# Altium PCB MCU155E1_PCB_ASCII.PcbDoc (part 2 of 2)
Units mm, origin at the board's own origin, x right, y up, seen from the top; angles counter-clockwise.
Board outline 32 x 29 mm, 4 copper layers (Top Layer, Layer 1, Layer 2, Bottom Layer), stack 1.567 mm thick; 102 components, 61 nets, 283 pads, 120 vias.
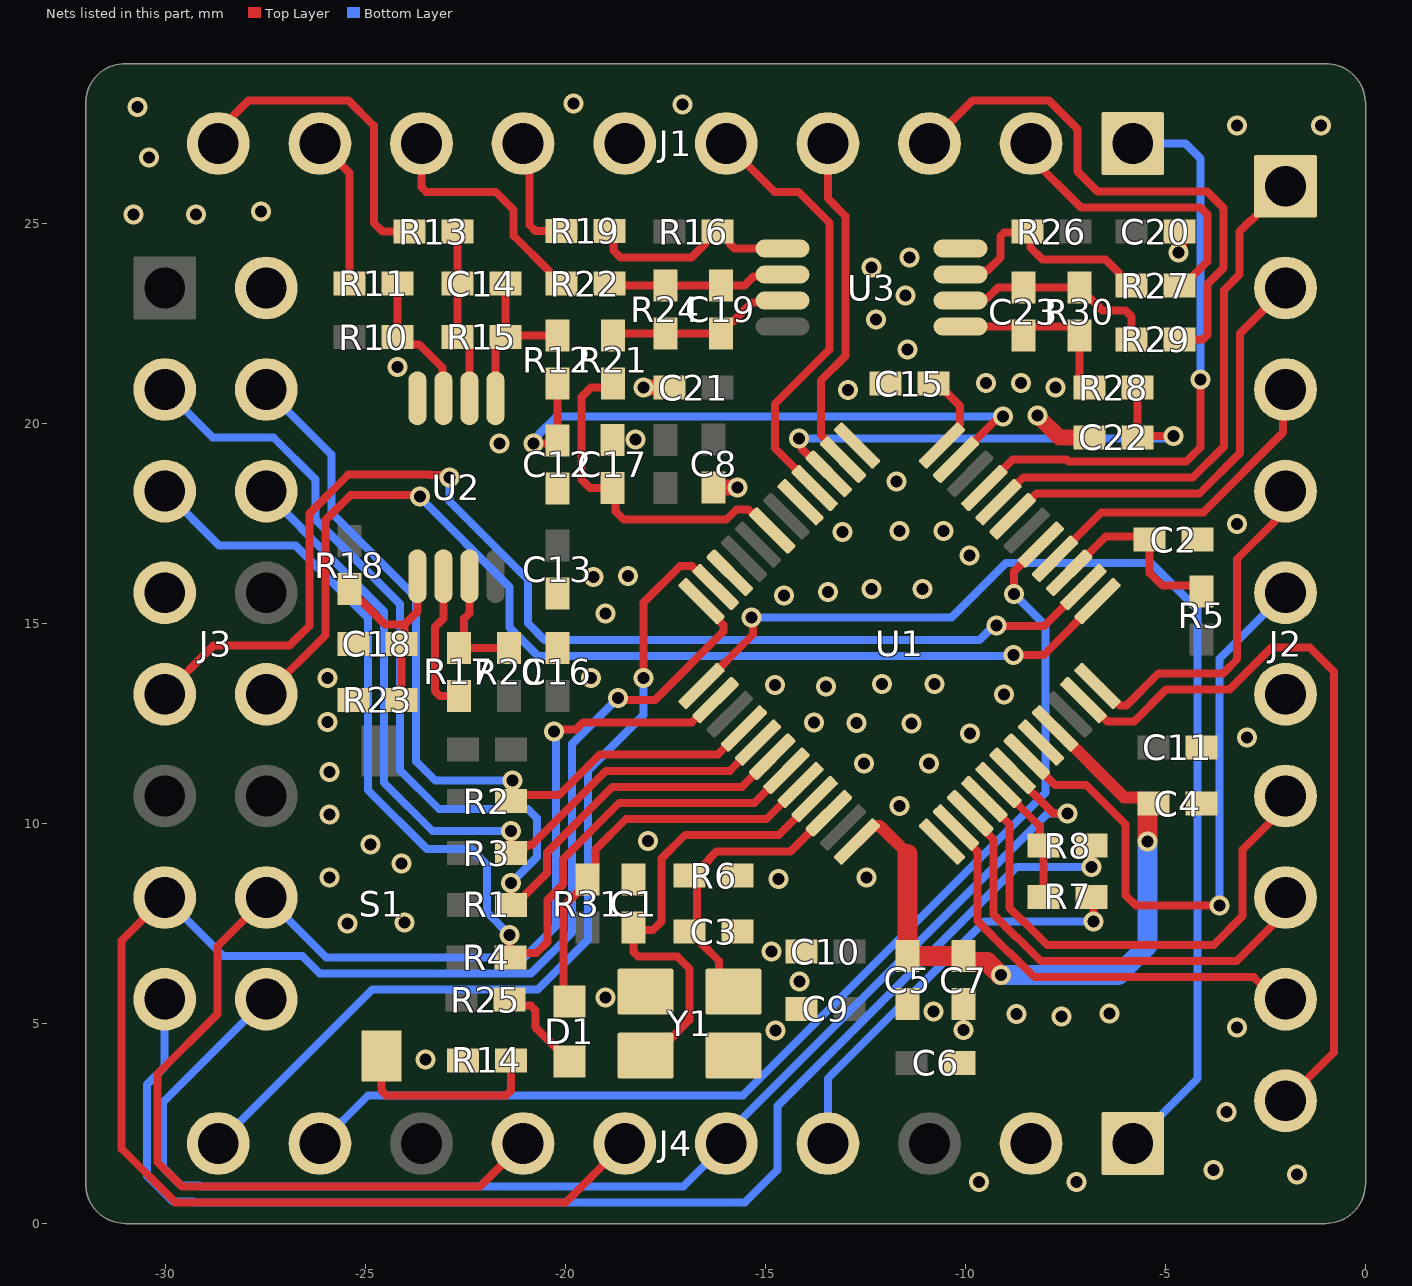
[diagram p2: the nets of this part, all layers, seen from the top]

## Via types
v1: diameter 0.5, hole 0.3, Top Layer to Bottom Layer, tented both sides, 120 vias

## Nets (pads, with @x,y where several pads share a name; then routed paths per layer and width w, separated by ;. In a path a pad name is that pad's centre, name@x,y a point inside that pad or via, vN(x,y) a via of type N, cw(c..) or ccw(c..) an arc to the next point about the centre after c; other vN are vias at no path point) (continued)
GND: C1.1 C2.2 C3.2 C4.1 C5.1 C6.2 C7.1 C8.2 C9.2 C10.2 C11.2 C12.2 C13.2 C15.2 C16.2 C17.2 C18.2 C20.2 C21.2 C22.2 J1.6 J2.6 J3.2 J3.7 J4.2 R6.1 R14.2 R23.1 U1.13 U1.17 U1.22 U1.37 U1.44 U2.4 U3.4 Y1.2 Y1.4 | length 3.6
  Top Layer w0.4: C18.2@-25.501,14.591 -25.401,14.491 C18.2@-25.301,14.491 ; v1(-18.05,20.9) C21.2@-17.4,20.9 ; C8.2@-16.3,18.4 -16.297,18.403 -15.703,18.403 v1(-15.7,18.405) ; v1(-8.2,20.2) -7.656,19.656 C22.2@-6.9,19.656 ; v1(-4.676,24.279) -4.663,24.292 -4.663,24.787 C20.2@-4.65,24.8
  other v1: -9.661,1.041 -7.231,1.041 -1.714,1.225 -3.8,1.343 -3.481,2.794 -23.5,4.1 -14.75,4.83 -10.051,4.833 -3.207,4.9 -7.599,5.179 -8.722,5.237 -6.4,5.256 -10.8,5.3 -19,5.65 -14.15,6.05 -14.85,6.8 -25.45,7.5 -24.024,7.52 -14.67,8.61 -25.9,8.651 -12.479,8.651 -24.1,9 -24.879,9.48 -17.943,9.558 -25.9,10.232 -11.649,10.438 -25.9,11.283 -12.531,11.502 -10.912,11.495 -2.959,12.149 -9.887,12.254 -12.729,12.517 -11.355,12.5 -25.95,12.544 -13.788,12.531 -9.038,13.226 -13.488,13.43 -14.768,13.465 -12.088,13.493 -10.77,13.493 -19.361,13.64 -25.95,13.644 -19,15.256 -14.533,15.705 -13.434,15.79 -12.35,15.86 -11.076,15.86 -19.294,16.163 -18.437,16.187 -9.9,16.703 -13.08,17.293 -11.649,17.312 -10.551,17.312 -3.207,17.491 -11.722,18.551 -21.65,19.5 -18.25,19.6 -12.932,20.843 -7.75,20.9 -9.493,21.01 -8.613,21.01 -24.206,21.408 -11.45,21.85 -12.233,22.606 -11.499,23.202 -12.35,23.9 -11.4,24.15 -30.8,25.224 -29.24,25.224 -27.608,25.3 -30.417,26.646 -3.207,27.454 -1.108,27.454 -30.698,27.909 -17.077,27.975 -19.801,27.998
IPM_FAULT: J4.1 U1.25 | length 28.5
  Top Layer w0.2: U1.25@-16.6,13.439 -15.308,14.731 -15.308,15.108 v1(-15.35,15.15)
  Bottom Layer w0.2: v1(-15.35,15.15) -10.35,15.15 -8.985,16.515 -5.365,16.515 -4.2,15.35 -4.2,3.62 J4.1@-5.82,2
IU_AD: C12.1 R12.2 U1.11 | length 15.7
  Top Layer w0.2: v1(-20.8,19.5) -20.277,19.5 C12.1@-20.2,19.577 R12.2@-20.2,21 ; U1.11@-10.236,19.096 -9.218,20.114 -9.12,20.114 v1(-9.063,20.171)
  Bottom Layer w0.2: v1(-20.8,19.5) -20.8,19.581 -20.663,19.718 -20.663,19.741 -20.232,20.171 v1(-9.063,20.171)
IU_N: J1.10 R13.1 | length 8.2
  Top Layer w0.2: J1.10@-28.68,27 -28.68,27.32 -27.925,28.075 -25.423,28.075 -24.793,27.445 -24.793,25.014 -24.579,24.8 R13.1@-23.9,24.8
IU_P: J1.9 R11.1 | length 3.8
  Top Layer w0.2: J1.9@-26.14,27 -25.4,26.26 R11.1@-25.4,23.5
IV_AD: C17.1 R21.2 U1.19 | length 8.7
  Top Layer w0.2: R21.2@-18.811,21 -18.911,20.9 -19.361,20.9 -19.6,20.661 -19.6,18.599 -19.39,18.388 C17.1@-18.82,18.388 -18.747,18.316 -18.747,17.806 -18.537,17.596 -15.979,17.596 -15.719,17.855 -15.43,17.855 U1.19@-14.903,17.328
IV_N: J1.8 R22.1 | length 6
  Top Layer w0.2: J1.8@-23.6,27 -23.6,25.911 -23.483,25.794 -21.746,25.794 -21.295,25.342 -21.295,24.693 -20.401,23.8 -20.401,23.7 -20.201,23.5 R22.1@-20.101,23.5
IV_P: J1.7 R19.1 | length 3
  Top Layer w0.2: J1.7@-21.06,27 -20.895,26.835 -20.895,24.958 -20.751,24.814 R19.1@-20.101,24.814
IW_AD: C22.1 R28.2 U1.15 | length 12.8
  Top Layer w0.2: v1(-14.16,19.621) -14.103,19.564 -14.103,19.38 -13.466,18.743 U1.15@-13.418,18.743 ; R28.2@-5.7,20.9 C22.1@-5.7,19.656 -5.671,19.685 v1(-4.8,19.685)
  Bottom Layer w0.2: v1(-14.16,19.621) -4.945,19.621 -4.881,19.685 v1(-4.8,19.685)
IW_N: J1.3 R29.1 | length 13.6
  Top Layer w0.2: J1.3@-10.9,27 -9.825,28.075 -7.915,28.075 -7.2,27.36 -7.2,26.3 -6.7,25.8 -3.96,25.8 -3.55,25.39 -3.55,23.891 -3.95,23.491 -3.95,22.219 -4.067,22.101 R29.1@-4.65,22.101
IW_P: J1.2 R27.1 | length 7.5
  Top Layer w0.2: J1.2@-8.36,27 -8.36,26.646 -7.114,25.4 -6.374,25.4 -5.326,25.4 -4.126,25.4 -3.95,25.224 -3.95,24.056 -4.35,23.656 -4.35,23.651 -4.55,23.451 R27.1@-4.65,23.451
LED1C: D1.2 R31.1 U1.32 | length 10.3
  Top Layer w0.2: D1.2@-19.9,5.55 -20.05,5.7 -20.05,7.924 -19.674,8.3 -19.65,8.3 -19.65,8.648 -19.4,8.898 R31.1@-19.38,8.898 ; R31.1@-19.45,8.6 -19.25,8.8 -19.25,9.35 -18.482,10.118 -14.971,10.118 U1.32@-14.125,10.964
MISC_IO: J4.9 U1.5 | length 28.6
  Top Layer w0.2: v1(-8.787,15.737) -8.787,16.303 U1.5@-8.114,16.975
  Bottom Layer w0.2: J4.9@-26.14,2 -24.933,3.207 -15.562,3.207 -8,10.769 -8,14.951 v1(-8.787,15.737)
MOTOR_TEMP_AD: J2.3 U1.4 | length 8.1
  Top Layer w0.2: U1.4@-7.761,16.621 -6.6,17.782 -4.054,17.782 -2.061,19.775 -2.061,20.789 J2.3@-2,20.85
NetC1_2: C1.2 U1.33 Y1.3 | length 11.7
  Top Layer w0.2: C1.2@-18.3,7.398 -18.3,6.792 -18.183,6.675 -17.206,6.675 -16.9,6.369 -16.9,5.094 -17.403,4.591 -17.403,4.535 -17.878,4.06 Y1.3@-18.003,4.06 ; C1.2@-18.216,7.334 -17.817,7.334 -17.6,7.551 -17.6,9.123 -17.005,9.718 -14.664,9.718 U1.33@-13.771,10.611
NetC3_1: C3.1 R6.2 U1.34 Y1.1 | length 7.4
  Top Layer w0.2: C3.1@-16.9,7.3 -16.8,7.3 -16.6,7.1 -16.6,7 -16.158,6.558 -16.158,6.158 Y1.1@-15.8,5.8 ; C3.1@-16.71,7.3 -16.71,8.55 -16.68,8.58 -16.68,8.819 -16.4,9.098 -16.4,9.123 -16.224,9.298 -14.377,9.298 U1.34@-13.418,10.257
NetC4_2: C4.2 C5.2 C7.2 U1.36 U1.45 | length 17.5
  Top Layer w0.3: U1.36@-12.711,9.55 -12.322,9.939 -12.145,9.939 -11.448,9.243 ; U1.45@-7.761,12.379 -6.032,10.65 -5.45,10.65 C4.2@-5.437,10.637
  Top Layer w0.5: -11.448,9.243 C5.2@-11.448,6.683 C7.2@-10.051,6.683 -10.051,6.583 -10.001,6.533 -9.451,6.533 -9.133,6.215 v1(-9.114,6.215) ; v1(-5.45,9.55) -5.45,10.157 -5.45,10.45 -5.4,10.5 C4.2@-5.3,10.5
  Bottom Layer w0.5: v1(-9.114,6.215) -6.179,6.215 -5.45,6.945 v1(-5.45,9.55)
NetC14_1: C14.1 R13.2 R15.1 U2.2 | length 4.3
  Top Layer w0.2: R13.2@-22.7,24.8 C14.1@-22.7,23.5 R15.1@-22.7,22.158 -22.602,22.158 -22.402,21.958 U2.2@-22.402,20.631
NetC14_2: C14.2 R12.1 R15.2 U2.1 | length 4.3
  Top Layer w0.2: U2.1@-21.752,20.631 -21.752,21.958 -21.552,22.158 R15.2@-21.5,22.158 ; C14.2@-21.5,23.5 R15.2@-21.5,22.158 ; R12.1@-20.2,22.2 -21.458,22.2 R15.2@-21.5,22.158
NetC15_1: C15.1 U1.12 | length 2.1
  Top Layer w0.2: C15.1@-10.8,21 -10.7,21 -10.138,20.438 -10.138,19.972 -10.589,19.52 U1.12@-10.589,19.45
NetC18_1: C18.1 R18.1 R23.2 U2.5 | length 5.1
  Top Layer w0.2: R18.1@-25.399,15.863 -25.399,15.763 -25.199,15.563 -25.099,15.563 -24.511,14.974 -24.026,14.974 ; C18.1@-24.101,14.491 -24.026,14.566 -24.026,14.974 ; R23.2@-24.1,13.094 C18.1@-24.101,14.491 ; U2.5@-23.702,16.181 -23.702,15.298 -24.026,14.974
NetC19_1: C19.1 R22.2 R24.1 U3.6 | length 4.4
  Top Layer w0.2: R22.2@-18.801,23.5 -18.753,23.452 R24.1@-17.498,23.451 -15.528,23.452 -15.303,23.677 -14.623,23.677 U3.6@-14.575,23.725
NetC19_2: C19.2 R21.1 R24.2 U3.7 | length 4.7
  Top Layer w0.2: R21.1@-18.811,22.2 -18.759,22.252 R24.2@-17.498,22.251 C19.2@-16.113,22.252 -16.113,22.352 -15.913,22.552 -15.813,22.552 -15.337,23.027 -14.623,23.027 U3.7@-14.575,23.075
NetC23_1: C23.1 R29.2 R30.1 U3.2 | length 5.3
  Top Layer w0.2: U3.2@-10.125,23.075 -10.087,23.113 -9.495,23.113 -9.441,23.168 -9.419,23.168 -9.187,23.4 C23.1@-8.548,23.4 R30.1@-7.146,23.4 -7.146,23.3 -6.971,23.125 -6.871,23.125 -6.572,22.826 -5.996,22.826 -5.85,22.679 R29.2@-5.85,22.101
NetC23_2: C23.2 R28.1 R30.2 U3.1 | length 4.5
  Top Layer w0.2: U3.1@-10.125,22.425 -7.346,22.425 -7.146,22.225 R30.2@-7.146,22.2 -7.146,21.1 -6.946,20.9 R28.1@-6.9,20.9
NetD1_1: D1.1 R25.2 | length 2.4
  Top Layer w0.2: R25.2@-21.4,5.6 -21.246,5.446 -20.867,5.446 -20.75,5.329 -20.75,4.9 D1.1@-19.9,4.05
NetR10_1: R10.1 R11.2 U2.3 | length 3.6
  Top Layer w0.2: R11.2@-24.2,23.5 R10.1@-24.2,22.158 -24.018,21.976 -23.658,21.976 -23.079,21.397 -23.079,20.658 U2.3@-23.052,20.631
NetR14_1: R14.1 S1.2 | length 5
  Top Layer w0.2: S1.2@-24.6,4.19 -24.6,3.324 -24.483,3.207 -21.482,3.207 -21.365,3.324 R14.1@-21.365,4.082
NetR16_1: R16.1 R19.2 U3.5 | length 5.4
  Top Layer w0.2: R19.2@-18.901,24.814 -18.806,24.719 -18.806,24.332 -18.626,24.152 -16.848,24.152 -16.5,24.5 -16.5,24.6 -16.3,24.8 R16.1@-16.2,24.8 -16.1,24.8 -15.9,24.6 -15.9,24.5 -15.775,24.375 U3.5@-14.575,24.375
NetR17_1: R17.1 R20.1 U2.7 | length 3.2
  Top Layer w0.2: U2.7@-22.402,16.181 -22.402,15.256 -22.533,15.125 -22.533,14.624 -22.664,14.493 R17.1@-22.664,14.393 R20.1@-21.407,14.393
NetR17_2: R17.2 U2.6 | length 3.6
  Top Layer w0.2: U2.6@-23.052,16.181 -23.052,15.129 -23.264,14.917 -23.264,13.31 -23.147,13.193 R17.2@-22.664,13.193
NetR26_1: R26.1 R27.2 U3.3 | length 5.8
  Top Layer w0.2: U3.3@-10.125,23.725 -9.621,23.725 -9.521,23.825 -9.447,23.825 -9.125,24.147 -9.125,24.683 -9.033,24.775 -8.475,24.775 R26.1@-8.45,24.8 -8.371,24.721 -8.371,24.396 -8.075,24.1 -6.499,24.1 -6.15,23.751 -6.15,23.651 -5.95,23.451 R27.2@-5.85,23.451
PC_RX: J3.9 U1.2 | length 30.1
  Top Layer w0.2: J3.9@-30.02,13.23 -28.801,14.449 -26.897,14.449 -26.405,14.941 -26.405,17.713 -26.399,17.718 -26.399,17.753 -25.432,18.72 -23.404,18.72 -23.393,18.71 -22.957,18.71 v1(-22.9,18.652) ; v1(-9.23,14.951) -9.217,14.938 -8.03,14.938 U1.2@-7.054,15.914
  Bottom Layer w0.2: v1(-22.9,18.652) -22.9,18.055 -20.932,16.086 -20.932,14.997 -20.525,14.59 -9.647,14.59 -9.287,14.951 v1(-9.23,14.951)
PC_TX: J3.10 U1.1 | length 27.4
  Top Layer w0.2: J3.10@-27.48,13.23 -26.001,14.709 -26.001,15.982 -25.999,15.984 -25.999,17.587 -25.379,18.207 -23.669,18.207 v1(-23.632,18.17) ; v1(-8.805,14.22) -8.041,14.22 U1.1@-6.7,15.561
  Bottom Layer w0.2: v1(-23.632,18.17) -23.632,18.149 -21.4,15.917 -21.4,14.9 -20.69,14.19 -8.834,14.19 v1(-8.805,14.22)
PWM_UH: J2.7 U1.40 | length 12.9
  Top Layer w0.2: U1.40@-9.529,10.611 -8.9,9.982 -8.9,7.891 -8.574,7.565 -8.555,7.565 -7.947,6.958 -3.803,6.958 -3.075,7.686 -3.075,9.346 -2,10.421 J2.7@-2,10.69
PWM_UL: J2.8 U1.39 | length 11.4
  Top Layer w0.2: U1.39@-9.882,10.257 -9.882,10.187 -9.3,9.604 -9.3,7.726 -8.74,7.165 -8.72,7.165 -8.113,6.558 -3.227,6.558 -2,7.785 J2.8@-2,8.15
PWM_VH: J2.9 U1.38 | length 11.1
  Top Layer w0.2: U1.38@-10.236,9.904 -10.236,9.833 -9.7,9.297 -9.7,7.56 -8.906,6.765 -8.886,6.765 -8.278,6.158 -2.792,6.158 -2.244,5.61 J2.9@-2,5.61
PWM_VL: J2.10 U1.47 | length 18.7
  Top Layer w0.2: U1.47@-7.054,13.086 -6.983,13.086 -6.45,12.553 -5.782,12.553 -4.985,13.35 -3.4,13.35 -2.35,14.4 -1.394,14.4 -0.794,13.8 -0.794,4.276 J2.10@-2,3.07
PWM_WH: J2.4 U1.48 | length 8.9
  Top Layer w0.2: U1.48@-6.7,13.439 -6.63,13.439 -6.143,12.953 -5.977,12.953 -5.18,13.75 -3.566,13.75 -3.207,14.109 -3.207,16.619 -2.258,17.567 -2.258,18.052 J2.4@-2,18.31
PWM_WL: J2.5 U1.43 | length 15.9
  Top Layer w0.2: U1.43@-8.468,11.672 -7.761,10.964 -6.983,10.964 -6,9.981 -6,8.209 -5.741,7.95 v1(-3.65,7.95)
  Bottom Layer w0.2: v1(-3.65,7.95) -3.65,14.12 J2.5@-2,15.77
RELAY: J4.10 U1.23 | length 22.8
  Top Layer w0.2: v1(-18.05,13.64) -18.05,15.525 -17.133,16.441 -16.844,16.441 -16.317,15.914 U1.23@-16.246,15.914
  Bottom Layer w0.2: J4.10@-28.68,2 -24.83,5.85 -20.694,5.85 -19.44,7.105 -19.44,11.327 -18.05,12.717 v1(-18.05,13.64)
SPI_CLK: J3.13 J4.6 U1.24 | length 42.6
  Top Layer w0.2: J3.13@-30.02,8.15 -31.095,7.075 -31.095,1.867 -29.753,0.525 -19.995,0.525 J4.6@-18.52,2 ; v1(-18.689,13.137) -18.643,13.09 -17.762,13.09 -16.055,14.797 -16.055,14.963 -16.6,15.507 U1.24@-16.6,15.561
  Bottom Layer w0.2: J3.13@-30.02,8.15 -28.555,6.685 -26.581,6.685 -26.146,6.25 -20.86,6.25 -19.84,7.27 -19.84,11.986 v1(-18.689,13.137)
SPI_PICO: J3.14 J4.7 U1.26 | length 35
  Top Layer w0.2: J3.14@-27.48,8.15 -28.7,6.93 -28.7,5.237 -30.204,3.732 -30.204,1.542 -29.587,0.925 -22.135,0.925 J4.7@-21.06,2 ; v1(-20.289,12.303) -20.24,12.353 -19.739,12.353 -19.561,12.531 -16.844,12.531 -16.289,13.086 U1.26@-16.246,13.086
  Bottom Layer w0.2: J3.14@-27.48,8.15 -25.98,6.65 -21.026,6.65 -20.24,7.436 -20.24,12.254 v1(-20.289,12.303)
SPI_POCI: R7.2 R8.2 U1.41 | length 3.3
  Top Layer w0.2: U1.41@-9.175,10.964 -8.144,9.933 -8.144,9.544 R8.2@-8.05,9.45 R7.2@-8.05,8.165
SPI_POCI(AI): J4.4 R7.1 | length 10.6
  Top Layer w0.2: R7.1@-6.85,8.165 -6.8,8.115 v1(-6.8,7.55) v1@-6.748,7.55
  Bottom Layer w0.2: J4.4@-13.44,2 -13.44,3.632 -9.522,7.55 v1(-6.8,7.55)
SPI_POCI(DAC): J3.15 R8.1 | length 33.4
  Top Layer w0.2: v1(-6.85,8.915) R8.1@-6.85,9.45
  Bottom Layer w0.2: J3.15@-30.02,5.61 -30.02,3.917 -30.46,3.477 -30.46,1.194 -29.816,0.55 -29.316,0.55 -29.291,0.525 -15.518,0.525 -14.7,1.343 -14.7,2.937 -8.722,8.915 v1(-6.85,8.915)
SPI_PTE: J3.16 J4.5 U1.42 | length 33.9
  Top Layer w0.2: U1.42@-8.822,11.318 -8.822,11.272 -7.8,10.25 v1(-7.45,10.25)
  Bottom Layer w0.2: J3.16@-27.48,5.61 -30.06,3.03 -30.06,1.398 -29.612,0.95 -29.15,0.95 -29.125,0.925 -17.055,0.925 J4.5@-15.98,2 -15.98,2.223 -7.953,10.25 v1(-7.45,10.25)
TCK: J3.4 R2.1 U1.28 | length 20.5
  Top Layer w0.2: R2.1@-21.365,10.557 R2.1@-21.33,10.592 ; v1(-21.33,11.078) R2.1@-21.33,10.592 ; U1.28@-15.539,12.379 -16.187,11.731 -19.14,11.731 -20.157,10.714 -21.208,10.714 R2.1@-21.33,10.592
  Bottom Layer w0.2: J3.4@-27.48,20.85 -25.85,19.22 -25.85,17.768 -23.734,15.652 -23.734,11.556 -23.256,11.078 v1(-21.33,11.078)
TDI: J3.5 R4.1 U1.31 | length 26.8
  Top Layer w0.2: v1(-21.4,7.217) -21.4,6.666 R4.1@-21.381,6.647 -21.269,6.759 -20.731,6.759 -20.45,7.039 -20.45,8.09 -20.065,8.475 -20.065,9.109 -18.656,10.518 -15.278,10.518 U1.31@-14.478,11.318
  Bottom Layer w0.2: J3.5@-30.02,18.31 -28.662,16.952 -26.749,16.952 -24.934,15.138 -24.934,10.834 -23.461,9.361 -22.364,9.361 -21.965,8.962 -21.965,7.782 v1(-21.4,7.217)
TDO: J3.6 R3.1 U1.29 | length 19.9
  Top Layer w0.2: v1(-21.365,9.807) R3.1@-21.365,9.262 -21.132,9.262 -20.932,9.462 -20.843,9.462 -18.988,11.318 -15.893,11.318 U1.29@-15.286,11.925
  Bottom Layer w0.2: J3.6@-27.48,18.31 -27.48,18.266 -26.6,17.386 -26.6,17.369 -24.534,15.303 -24.534,11.022 -23.319,9.807 v1(-21.365,9.807)
TIPM_AD: J2.2 U1.7 | length 10.9
  Top Layer w0.2: U1.7@-8.822,17.682 -8.798,17.682 -8.224,18.256 -4.145,18.256 -3.141,19.26 -3.141,22.249 J2.2@-2,23.39
TMS: J3.3 R1.1 U1.30 | length 27.6
  Top Layer w0.2: v1(-21.365,8.512) R1.1@-21.365,7.967 -21.265,7.967 -20.465,8.767 -20.465,9.275 -18.822,10.918 -15.586,10.918 U1.30@-14.832,11.672
  Bottom Layer w0.2: J3.3@-30.02,20.85 -28.827,19.657 -27.306,19.657 -26.25,18.6 -26.25,17.602 -24.134,15.486 -24.134,11.334 -23.157,10.357 -20.939,10.357 -20.715,10.133 -20.715,9.162 v1(-21.365,8.512)
VDC_AD: J2.1 U1.8 | length 13.4
  Top Layer w0.2: U1.8@-9.175,18.036 -8.555,18.656 -4.311,18.656 -3.541,19.426 -3.541,23.334 -3.15,23.725 -3.15,24.8 -2.89,25.06 -2.87,25.06 J2.1@-2,25.93
VU_AD: J1.4 U1.14 | length 8.6
  Top Layer w0.2: J1.4@-13.44,27 -13.44,25.624 -13,25.184 -13,21.691 -13.61,21.081 -13.61,19.713 -13.064,19.167 U1.14@-13.064,19.096
VV_AD: J1.1 U1.9 | length 14.9
  Top Layer w0.2: U1.9@-9.529,18.389 -8.822,19.096 -7.464,19.096 -7.424,19.056 -4.477,19.056 -4.126,19.407 v1(-4.126,21.1)
  Bottom Layer w0.2: J1.1@-5.82,27 -4.5,27 -4.126,26.626 v1(-4.126,21.1)
VW_AD: J1.5 U1.16 | length 11
  Top Layer w0.2: J1.5@-15.98,27 -14.774,25.794 -14.175,25.794 -13.4,25.019 -13.4,21.857 -14.763,20.494 -14.763,19.381 U1.16@-13.771,18.389
XRSn: C2.1 R5.1 U1.3 | length 4.7
  Top Layer w0.2: U1.3@-7.407,16.268 -6.504,17.171 -5.471,17.171 C2.1@-5.4,17.1 -5.4,16.269 -5.081,15.95 -4.25,15.95 R5.1@-4.1,15.8
pads on no net: J3.8 J3.11 J3.12 J4.8 LBL1.0 M46.1 M46.2 M47.1 M49.1 M49.2 M49_1.2 M49_2.2 M50.1 M50.2 M51.1 M51.2 M52.1 M52.2 M53.1 M54.1 M55.1 M56.2 M56_1.2 M56_2.2 M57.2 M57_1.2 M57_2.2 M57_2_1.2 M57_2_2.2 M58.2 M58_1.2 M58_2.2 M58_2_1.2 M59.2 M59_1.2 M60.2 M60_1.2 M61.2 U1.6 U1.10 U1.20 U1.21

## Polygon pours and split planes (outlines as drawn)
GND on Top Layer "T-G" (solid, remove dead copper, pour order 0): -30.6,28.6 ccw(c-30.6,27.6) -31.6,27.6 -31.6,1.4 ccw(c-30.6,1.4) -30.6,0.4 -1.4,0.4 ccw(c-1.4,1.4) -0.4,1.4 -0.4,27.6 ccw(c-1.4,27.6) -1.4,28.6
GND on Layer 1 "G1-G" (solid, remove dead copper, pour order 1): -30.6,28.6 ccw(c-30.6,27.6) -31.6,27.6 -31.6,1.4 ccw(c-30.6,1.4) -30.6,0.4 -1.4,0.4 ccw(c-1.4,1.4) -0.4,1.4 -0.4,27.6 ccw(c-1.4,27.6) -1.4,28.6
GND on Layer 2 "G2-G" (solid, remove dead copper, pour order 2): -30.6,28.6 ccw(c-30.6,27.6) -31.6,27.6 -31.6,1.4 ccw(c-30.6,1.4) -30.6,0.4 -1.4,0.4 ccw(c-1.4,1.4) -0.4,1.4 -0.4,27.6 ccw(c-1.4,27.6) -1.4,28.6
GND on Bottom Layer "B-G" (solid, remove dead copper, pour order 3): -30.6,28.6 ccw(c-30.6,27.6) -31.6,27.6 -31.6,1.4 ccw(c-30.6,1.4) -30.6,0.4 -1.4,0.4 ccw(c-1.4,1.4) -0.4,1.4 -0.4,27.6 ccw(c-1.4,27.6) -1.4,28.6

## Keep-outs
Keep-Out Layer:
  text ".Layer_Name" at -107.864,-32.255 h1.52

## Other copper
Top Layer:
  text ".Layer_Name" at -107.864,-32.255 h1.52
Bottom Layer:
  text ".Layer_Name" at -107.864,-32.255 h1.52

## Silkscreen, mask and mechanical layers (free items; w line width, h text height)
Top Overlay:
  lines w0.1: -9.14,4.717 -3.19,4.717 ; -9.14,5.376 -3.19,5.376 ; -6.445,3.991 -6.445,6.741 ; -9.19,3.97 -3.19,3.97 -3.19,6.77 -9.19,6.77 -9.19,3.97
  text "1" at -26.773,10.521 h0.4
  text "S1 /  / 1-OFF / 0-ON" at -9.355,4.106 h0.4
  text "Boot Mode / Flash / SCI/Wait" at -6.321,4.106 h0.4
  text "0" at -26.773,3.907 h0.4
  text "拼板" at 263.809,-23.566 h5
  text ".Layer_Name" at -107.864,-32.255 h1.52
Bottom Overlay:
  text "'.PRJ_Number'.PCB_Rev" at -15.867,10.118 h1.52 r270
  text "'.PRJ_Title'" at -14.15,4.757 h1.52 r270
  text ".Layer_Name" at -107.864,-32.255 h1.52
Top Paste:
  text ".Layer_Name" at -107.864,-32.255 h1.52
Bottom Paste:
  text ".Layer_Name" at -107.864,-32.255 h1.52
Top Solder:
  text ".Layer_Name" at -107.864,-32.255 h1.52
  text ".Layer_Name" at -107.864,-32.255 h1.52
Bottom Solder:
  text ".Layer_Name" at -107.864,-32.255 h1.52
Drill Guide:
  text ".Layer_Name" at -107.864,-32.255 h1.52
M1 Board Outline:
  drawing of 210 lines, arcs and shapes, not listed
  text ".Layer_Name" at -107.864,-32.255 h1.52
M2 Board Dimensions:
  rectangle: -122.52,-17.435 -119.345,-14.26
  rectangle: -119.345,-20.61 -109.82,-17.435
  lines w0.178: -122.52,-17.435 -97.12,-17.435 ; -119.345,-20.61 -119.345,-14.26 ; -116.17,-20.61 -116.17,-14.26 ; -109.82,-20.61 -109.82,-14.26 ; -103.47,-20.61 -103.47,-14.26 ; -122.52,-20.61 -97.12,-20.61 -97.12,-14.26 -122.52,-14.26 -122.52,-20.61
  text ".Layer_Name" at -107.864,-32.255 h1.52
M3 3D STEP Top:
  text ".Layer_Name" at -107.864,-32.255 h1.52
M4 3D STEP Bottom:
  text ".Layer_Name" at -107.864,-32.255 h1.52
M5 Assembly Top:
  lines w0.254: -129.937,-34.076 37.703,-34.076 ; -129.937,-28.911 37.754,-28.911 ; -129.937,-23.746 -129.937,-39.24 -28.21,-39.24 37.754,-39.24 37.754,-23.746 -129.924,-23.746 -129.924,-39.24 -89.906,-39.24 ; -67.326,-39.24 -67.326,-23.746 ; -35.144,-28.911 -35.144,-23.746 ; -13.808,-28.911 -13.808,-23.746 ; 1.991,-39.406 1.991,-34.254
  text "COMPONENTS MARKED 'DNP' SHOULD NOT BE POPULATED." at -93.221,-18.539 h0.8
  text "ASSEMBLY VARIANT:" at -93.234,-21.473 h0.8
  text ".VariantName" at -66.919,-21.473 h0.8
  text "PCB VIEWED FROM TOP SIDE" at -128.324,-27.103 h1.52
  text "BOARD #:" at -65.421,-27.103 h1.52
  text ".PRJ_Number" at -51.565,-27.103 h1.52
  text "REV:" at -30.115,-27.103 h1.52
  text ".PCB_Rev" at -22.711,-27.103 h1.52
  text "SVN REV:" at -8.83,-27.103 h1.52
  text ".VersionControl_RevNumber" at 4.023,-27.103 h1.52
  text "TID #:" at -65.421,-32.268 h1.52
  text ".TID" at -51.565,-32.268 h1.52
  text "PLOT NAME =" at -128.324,-37.484 h1.52
  text ".plot_File_Name" at -107.864,-37.484 h1.52
  text "GENERATED    :" at -65.37,-37.484 h1.52
  text ".Print_Date" at -43.285,-37.484 h1.52
  text ".Print_Time" at -24.768,-37.484 h1.52
  text "TEXAS INSTRUMENTS" at 7.35,-37.484 h1.52
M6 Assembly Bottom:
  lines w0.254: -129.95,-28.924 37.741,-28.924 ; -129.899,-34.088 37.741,-34.088 ; -94.186,-39.418 -94.186,-34.266 ; -78.388,-28.924 -78.388,-23.759 ; -57.052,-28.924 -57.052,-23.759 ; -24.87,-39.253 -24.87,-23.759 ; -2.289,-39.253 37.729,-39.253 37.729,-23.759 -129.95,-23.759 -129.95,-39.253 -63.986,-39.253 37.741,-39.253 37.741,-23.759
  text "COMPONENTS MARKED 'DNP' SHOULD NOT BE POPULATED." at 32.471,-18.527 h0.8
  text ".VariantName" at 5.953,-21.473 h0.8
  text "ASSEMBLY VARIANT:" at 32.344,-21.473 h0.8
  text ".VersionControl_RevNumber" at -96.218,-27.116 h1.52
  text "SVN REV:" at -83.366,-27.116 h1.52
  text ".PCB_Rev" at -69.485,-27.116 h1.52
  text "REV:" at -62.081,-27.116 h1.52
  text ".PRJ_Number" at -40.63,-27.116 h1.52
  text "BOARD #:" at -26.775,-27.116 h1.52
  text "PCB VIEWED FROM BOTTOM SIDE" at 36.128,-27.116 h1.52
  text ".TID" at -40.63,-32.281 h1.52
  text "TID #:" at -26.775,-32.281 h1.52
  text "TEXAS INSTRUMENTS" at -99.546,-37.496 h1.52
  text ".Print_Time" at -67.427,-37.496 h1.52
  text ".Print_Date" at -48.911,-37.496 h1.52
  text "GENERATED    :" at -26.826,-37.496 h1.52
  text ".plot_File_Name" at 15.669,-37.496 h1.52
  text "PLOT NAME =" at 36.128,-37.496 h1.52
M9 Title Sheet:
  lines w0.254: -135.004,16.005 -129.924,16.005 ; -135.004,76.33 -129.924,76.33 ; -135.004,136.655 -129.924,136.655 ; -71.504,-44.32 -71.504,-39.24 ; -71.504,191.9 -71.504,196.98 ; -8.004,-44.32 -8.004,-39.24 ; -8.004,191.9 -8.004,196.98 ; 38.033,-39.24 38.033,-23.746 164.589,-23.746 ; 55.496,-44.32 55.496,-39.24 ; 55.496,191.9 55.496,196.98 ; 118.996,-44.32 118.996,-39.24 ; 118.996,191.9 118.996,196.98 ; 164.589,-39.24 164.589,-23.746 ; 164.589,-31.366 240.789,-31.366 ; 164.589,-16.126 240.789,-16.126 ; 164.614,-1.039 240.814,-1.039 ; 182.496,-44.32 182.496,-39.24 ; 182.496,191.9 182.496,196.98 ; 202.816,-38.986 202.816,-23.746 ; 240.789,-23.746 164.589,-23.746 ; 240.789,-8.506 164.589,-8.506 ; 240.916,-8.76 240.916,-39.24 ; 240.916,11.674 164.614,11.674 164.589,11.674 164.589,-1.039 164.589,-8.506 ; 240.916,16.005 245.996,16.005 ; 240.916,76.33 245.996,76.33 ; 240.916,136.655 245.996,136.655 ; 164.589,-23.746 164.589,-8.506 ; 240.916,-39.24 240.916,191.9 -129.924,191.9 -129.924,-39.24 240.916,-39.24 ; -135.004,-44.32 -135.004,196.98 245.996,196.98 245.996,-44.32 -135.004,-44.32
  text "1" at -103.728,193.678 h1.78
  text "2" at -40.338,193.678 h1.78
  text "3" at 22.891,193.678 h1.78
  text "4" at 86.56,193.678 h1.78
  text "5" at 150.035,193.678 h1.78
  text "6" at 213.662,193.678 h1.78
  text "A" at -133.099,164.645 h1.78
  text "A" at 242.821,164.645 h1.78
  text "B" at -133.099,104.193 h1.78
  text "B" at 242.821,104.193 h1.78
  text "C" at -133.099,43.868 h1.78
  text "C" at 242.821,43.868 h1.78
  text "PROJECT TITLE:" at 165.605,-3.401 h1.14
  text ".PRJ_Title" at 166.875,-6.788 h1.78
  text "DESIGNED FOR:" at 165.605,-11.046 h1.14
  text ".PRJ_Customer" at 166.875,-14.602 h1.78
  text "D" at -133.099,-16.33 h1.78
  text "D" at 242.821,-16.33 h1.78
  text "FILE NAME:" at 165.605,-18.666 h1.14
  text ".PCB_File_Name_No_Path" at 166.875,-21.714 h1.78
  text "Texas Instruments (TI) and/or its licensors do not warrant the accuracy or completeness of this specification" at 39.38,-25.825 h1.14
  text "ENGINEER:" at 165.605,-26.032 h1.14
  text "LAYOUT BY:" at 203.832,-26.032 h1.14
  text "or any information contained therein. TI and/or its licensors do not warrant that this design will meet" at 38.237,-28.687 h1.14
  text ".PRJ_Engineer" at 166.875,-29.969 h1.78
  text ".PCB_Layout" at 205.115,-29.969 h1.78
  text "the specifications, will be suitable for your application or fit for any particular purpose, or will operate in" at 38.237,-31.549 h1.14
  text ".Layer_Name" at -107.864,-32.255 h1.52
  text "ALTIUM DESIGNER VERSION:" at 203.832,-33.906 h1.14
  text "an implementation. TI and/or its licensors do not warrant that the design is production worthy. You should" at 38.237,-34.41 h1.14
  text "completely validate and test your design implementation to confirm the system functionality for your application." at 39.38,-37.272 h1.14
  text ".print_Scale" at 166.875,-37.293 h1.78
  text ".Application_BuildNumber" at 205.115,-37.293 h1.78
  text "1" at -103.728,-42.542 h1.78
  text "2" at -40.338,-42.542 h1.78
  text "3" at 22.891,-42.542 h1.78
  text "4" at 86.56,-42.542 h1.78
  text "5" at 150.035,-42.542 h1.78
  text "6" at 213.662,-42.542 h1.78
M10 Fab Notes:
  drawing of 189 lines, arcs and shapes, not listed
  text "DESIGN INFORMATION" at 191.983,150.997 h1.52
  text "MIN. TRACK WIDTH:" at 175.611,147.641 h1.52
  text "8" at 203.456,147.641 h1.52
  text "MIL" at 207.387,147.641 h1.52
  text "MIN. CLEARANCE:" at 175.611,144.489 h1.52
  text "MIL" at 207.387,144.489 h1.52
  text "8" at 203.68,144.35 h1.52
  text "MIN. VIA PAD SIZE:" at 175.611,141.336 h1.52
  text "19" at 202.694,141.336 h1.52
  text "MIL" at 207.387,141.336 h1.52
  text "0.05mm (2MIL)" at 193.264,138.036 h1.52
  text "MINIMUM ANNULAR RING" at 167.249,137.827 h1.52
  text "EXTERNAL" at 211.248,137.827 h1.52
  text "PER" at 172.329,135.03 h1.52
  text "IPC-D-275 CLASS 2 LEVEL C" at 177.917,135.03 h1.52
  text "MIL, HOLES" at 215.718,132.478 h1.52
  text "+/-" at 205.75,132.26 h1.52
  text "+/-" at 227.441,132.26 h1.52
  text "REGISTRATION TOLERANCES:" at 167.249,132.233 h1.52
  text "METAL" at 197.723,132.233 h1.52
  text "5" at 212.359,132.233 h1.52
  text "3" at 233.517,132.233 h1.52
  text "MIL" at 236.47,132.233 h1.52
  text "HOLE SIZE TOLERANCE (UNLESS OTHERWISE SPECIFIED):" at 167.249,129.736 h1.52
  text "+/-" at 227.441,129.663 h1.52
  text "3" at 233.517,129.636 h1.52
  text "MIL" at 236.47,129.636 h1.52
  text "MATERIAL:" at 165.35,126.139 h1.52
  text "FR-4 High Tg" at 190.406,122.875 h1.52
  text "X" at 186.737,122.672 h1.52
  text "FR-4" at 176.043,122.557 h1.52
  text "OTHER" at 213.838,122.557 h1.52
  text "62 MIL (1.6mm) +/-10%" at 184.174,118.924 h1.52
  text "X" at 181.123,118.862 h1.52
  text "THICKNESS:" at 167.249,118.716 h1.52
  text "OTHER" at 216.81,118.716 h1.52
  text "TOLERANCE:" at 167.249,115.202 h1.52
  text "X" at 188.794,115.202 h1.52
  text "ANSI IPC-6012 TYPE 3 CLASS 2" at 193.316,115.202 h1.52
  text "OTHER +/-" at 193.315,111.54 h1.52
  text "BOW & TWIST:" at 167.249,107.852 h1.52
  text "X" at 188.794,107.852 h1.52
  text "ANSI IPC-6012 TYPE 3 CLASS 2" at 193.316,107.852 h1.52
  text "OTHER +/-" at 193.315,104.126 h1.52
  text "DRILLING:" at 165.35,100.808 h1.52
  text "NC_DRILL FILES" at 210.079,98.137 h1.52
  text "REFERENCE:" at 167.249,98.037 h1.52
  text "X" at 183.943,98.034 h1.52
  text "AS SHOWN" at 188.464,98.037 h1.52
  text "X" at 206.828,98.037 h1.52
  text "OTHER" at 217.648,94.423 h1.52
  text "PTH COPPER THICKNESS:" at 167.241,94.334 h1.52
  text "X" at 196.177,94.334 h1.52
  text "20-30 um" at 199.428,94.334 h1.52
  text "BOARD FINISH:" at 165.35,90.585 h1.52
  text "SILKSCREEN:" at 169.292,87.788 h1.52
  text "X" at 193.62,87.788 h1.52
  text "TOP" at 196.592,87.788 h1.52
  text "X" at 206.574,87.788 h1.52
  text "BOTTOM" at 209.571,87.788 h1.52
  text "SILKSCREEN COLOR:" at 169.292,83.846 h1.52
  text "X" at 193.595,83.846 h1.52
  text "WHITE" at 196.592,83.846 h1.52
  text "OTHER" at 209.571,83.846 h1.52
  text "X" at 196.922,80.202 h1.52
  text "GREEN" at 199.919,80.202 h1.52
  text "OTHER" at 215.616,80.202 h1.52
  text "SOLDER RESIST COLOR:" at 169.292,80.028 h1.52
  text "X" at 196.922,76.284 h1.52
  text "MATTE" at 199.919,76.284 h1.52
  text "SEMI-GLOSS" at 215.605,76.268 h1.52
  text "IMMERSION GOLD (ENIG)" at 192.299,71.896 h1.52
  text "ENEPIG" at 226.273,71.712 h1.52
  text "SURFACE FINISH:" at 165.35,71.687 h1.52
  text "HASL" at 219.717,68.312 h1.52
  text "IMM. TIN/SILVER OR EQUIV" at 173.72,68.199 h1.52
  text "X" at 205.558,68.099 h1.52
  text "OTHER" at 210.079,68.099 h1.52
  text "ARRAY/PANEL:" at 165.35,64.153 h1.52
  text "CUT AND TRIM PER M1 BOARD OUTLINE" at 192.299,63.944 h1.52
  text "N.C. ROUTE" at 192.299,60.49 h1.52
  text "X" at 209.775,60.49 h1.52
  text "V. SCORE" at 214.296,60.49 h1.52
  text "CERTIFICATION:" at 165.35,57.21 h1.52
  text "MATERIALS AND WORKMANSHIP FOR ALL PCBS" at 183.765,57.21 h1.52
  text "TO MEET OR EXCEED THE REQUIREMENTS OF:" at 183.765,54.821 h1.52
  text "X" at 174.558,51.554 h1.52
  text "ANSI IPC-A-600F CLASS ->" at 177.809,51.554 h1.52
  text "X" at 219.668,51.554 h1.52
  text "2" at 222.462,51.554 h1.52
  text "1" at 214.461,51.516 h1.52
  text "3" at 231.453,51.516 h1.52
  text "X" at 195.182,47.803 h1.52
  text "RoHS" at 198.433,47.803 h1.52
  text "OTHER" at 214.801,47.803 h1.52
  text "PER ORDER" at 224.887,47.803 h1.52
  text "ALL BOARDS MUST MEET OR EXCEED UL94-V0 REQUIREMENTS." at 166.049,43.895 h1.52
  text "PCB MUST BEAR THE UL94V-0 UL REGISTERED MATERIAL ID NUMBER" at 166.049,40.947 h1.52
  text "ADDITIONAL REQUIREMENTS:" at 165.35,36.644 h1.52
  text "MICROSECTION:" at 167.249,33.923 h1.52
  text "YES" at 190.255,33.923 h1.52
  text "REQUIRED" at 212.137,30.257 h1.52
  text "BARE BOARD ELEC. TEST:" at 167.249,30.185 h1.52
  text "NONE" at 200.415,30.185 h1.52
  text "X" at 209.14,30.185 h1.52
  text "PER ORDER" at 227.173,30.185 h1.52
  text "XX MIL VIAS REQUIRE NON-CONDUCTIVE FILL AND PLANARIZE" at 171.52,24.979 h1.5
  text "XX MIL VIAS REQUIRE CONDUCTIVE FILL AND PLANARIZE" at 171.723,22.338 h1.52
  text "OUTER XX MIL TRACES REQUIRE 50 OHM SINGLE-ENDED IMPEDANCE" at 171.698,18.188 h1.47
  text "LAYER 2 & 3 (INNER LAYERS) XX MIL WIDE, XX MIL SPACE / TRACES REQUIRE 100 OHM DIFFERENTIAL IMPEDANCE" at 171.495,12.201 h1.52
  text ".Layer_Name" at -107.864,-32.255 h1.52
M11 Gerber Information:
  lines w0.254: -129.937,-34.076 37.703,-34.076 ; -129.937,-28.911 37.754,-28.911 ; -129.937,-23.746 -129.937,-39.24 -28.21,-39.24 37.754,-39.24 37.754,-23.746 -129.924,-23.746 -129.924,-39.24 -89.906,-39.24 ; -67.326,-39.24 -67.326,-23.746 ; -35.144,-28.911 -35.144,-23.746 ; -13.808,-28.911 -13.808,-23.746 ; 1.991,-39.406 1.991,-34.254
  text "ALL ARTWORK VIEWED FROM TOP SIDE" at -128.324,-27.103 h1.52
  text "BOARD #:" at -65.421,-27.103 h1.52
  text ".PRJ_Number" at -51.565,-27.103 h1.52
  text "REV:" at -30.115,-27.103 h1.52
  text ".PCB_Rev" at -22.711,-27.103 h1.52
  text "SVN REV:" at -8.83,-27.103 h1.52
  text ".VersionControl_RevNumber" at 4.023,-27.103 h1.52
  text "LAYER NAME =" at -128.324,-32.255 h1.52
  text "TID #:" at -65.421,-32.268 h1.52
  text ".TID" at -51.565,-32.268 h1.52
  text "PLOT NAME =" at -128.324,-37.484 h1.52
  text ".plot_File_Name" at -107.864,-37.484 h1.52
  text "GENERATED    :" at -65.37,-37.484 h1.52
  text ".Print_Date" at -43.285,-37.484 h1.52
  text ".Print_Time" at -24.768,-37.484 h1.52
  text "TEXAS INSTRUMENTS" at 7.35,-37.484 h1.52
M12 Stackup:
  drawing of 196 lines, arcs and shapes, not listed
  text "Layer" at 126.694,189.574 h1.52
  text "Name" at 133.072,189.574 h1.52
  text "Material" at 145.406,189.574 h1.52
  text "Thickness" at 156.489,189.574 h1.52
  text "Constant" at 165.593,189.574 h1.52
  text "Board Layer Stack" at 174.019,189.574 h1.52
  text "Top Overlay" at 133.072,186.526 h1.52
  text "Top Solder" at 133.072,183.478 h1.52
  text "Solder Resist" at 145.406,183.478 h1.52
  text "0.010mm" at 156.489,183.478 h1.52
  text "3.5" at 165.593,183.478 h1.52
  text "1" at 126.694,180.43 h1.52
  text "Top Layer" at 133.072,180.43 h1.52
  text "CF-004" at 145.406,180.43 h1.52
  text "0.035mm" at 156.489,180.43 h1.52
  text "Dielectric 1" at 133.072,177.382 h1.52
  text "PP-023" at 145.406,177.382 h1.52
  text "0.218mm" at 156.489,177.382 h1.52
  text "4.5" at 165.593,177.382 h1.52
  text "2" at 126.693,174.334 h1.52
  text "Layer 1" at 133.072,174.334 h1.52
  text "CF-004" at 145.406,174.334 h1.52
  text "0.035mm" at 156.489,174.334 h1.52
  text "Dielectric1" at 133.072,171.286 h1.52
  text "Core-042" at 145.406,171.286 h1.52
  text "0.991mm" at 156.489,171.286 h1.52
  text "4.6" at 165.593,171.286 h1.52
  text "3" at 126.694,168.238 h1.52
  text "Layer 2" at 133.072,168.238 h1.52
  text "CF-004" at 145.406,168.238 h1.52
  text "0.035mm" at 156.489,168.238 h1.52
  text "Dielectric 2" at 133.072,165.19 h1.52
  text "PP-023" at 145.406,165.19 h1.52
  text "0.218mm" at 156.489,165.19 h1.52
  text "4.5" at 165.593,165.19 h1.52
  text "4" at 126.694,162.142 h1.52
  text "Bottom Layer" at 133.072,162.142 h1.52
  text "CF-004" at 145.406,162.142 h1.52
  text "0.035mm" at 156.489,162.142 h1.52
  text "Bottom Solder" at 133.072,159.094 h1.52
  text "Solder Resist" at 145.406,159.094 h1.52
  text "0.010mm" at 156.489,159.094 h1.52
  text "3.5" at 165.593,159.094 h1.52
  text "Bottom Overlay" at 133.072,156.046 h1.52
  text ".Layer_Name" at -107.864,-32.255 h1.52
M13 Component Bodies Top:
  text ".Layer_Name" at -107.864,-32.255 h1.52
M14 Component Bodies Bottom:
  text ".Layer_Name" at -107.864,-32.255 h1.52
M15 Courtyards Top:
  text ".Layer_Name" at -107.864,-32.255 h1.52
M16 Courtyards Bottom:
  text ".Layer_Name" at -107.864,-32.255 h1.52
Drill Drawing:
  circle w0.254: c-123.564,89.741 r0.847
  lines w0.254: -124.411,92.704 -122.717,92.704 -122.717,94.397 -124.411,94.397 -124.411,92.704 ; -124.411,98.207 -122.717,98.207 -123.564,96.514 -124.411,98.207
  lines w0.381: -125.93,87.751 54.666,87.751 ; -125.93,99.181 54.666,99.181 ; -111.937,83.941 -111.937,102.991 ; -96.955,83.941 -96.955,102.991 ; -69.023,83.941 -69.023,102.991 ; -56.174,83.941 -56.174,102.991 ; -37.536,83.941 -37.536,102.991 ; 0.553,83.941 0.553,102.991 ; 15.535,83.941 15.535,102.991 ; 34.478,83.941 34.478,102.991 ; -125.93,83.941 54.666,83.941 54.666,102.991 -125.93,102.991 -125.93,83.941
  text "Symbol" at -123.644,100.324 h1.83
  text "Count" at -110.794,100.324 h1.83
  text "Hole Size" at -95.812,100.324 h1.83
  text "Plated" at -67.88,100.324 h1.83
  text "Hole Type" at -55.031,100.324 h1.83
  text "Drill Layer Pair" at -36.393,100.324 h1.83
  text "Via/Pad" at 1.696,100.324 h1.83
  text "Pad Shape" at 16.678,100.324 h1.83
  text "Template" at 35.621,100.324 h1.83
  text "4" at -110.794,96.514 h1.52
  text "2.000mm (78.74mil)" at -95.812,96.514 h1.52
  text "NPTH" at -67.88,96.514 h1.52
  text "Round" at -55.031,96.514 h1.52
  text "Top Layer - Bottom Layer" at -36.393,96.514 h1.52
  text "Pad" at 1.696,96.514 h1.52
  text "Rounded" at 16.678,96.514 h1.52
  text "c200hn200" at 35.621,96.514 h1.52
  text "46" at -110.794,92.704 h1.52
  text "1.020mm (40.16mil)" at -95.812,92.704 h1.52
  text "PTH" at -67.88,92.704 h1.52
  text "Round" at -55.031,92.704 h1.52
  text "Top Layer - Bottom Layer" at -36.393,92.704 h1.52
  text "Pad" at 1.696,92.704 h1.52
  text "(Mixed)" at 16.678,92.704 h1.52
  text "(Mixed)" at 35.621,92.704 h1.52
  text "120" at -110.794,88.894 h1.52
  text "0.300mm (11.81mil)" at -95.812,88.894 h1.52
  text "PTH" at -67.88,88.894 h1.52
  text "Round" at -55.031,88.894 h1.52
  text "Top Layer - Bottom Layer" at -36.393,88.894 h1.52
  text "Via" at 1.696,88.894 h1.52
  text "Rounded" at 16.678,88.894 h1.52
  text "v50h30m0mx0" at 35.621,88.894 h1.52
  text "170 Total" at -110.794,85.084 h1.52
  text ".Layer_Name" at -107.864,-32.255 h1.52
M17 Embedded Cavity:
  text ".Layer_Name" at -107.864,-32.255 h1.52
M18 Embedded Assembly:
  text ".Layer_Name" at -107.864,-32.255 h1.52
M19 Embedded Keepout:
  text ".Layer_Name" at -107.864,-32.255 h1.52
